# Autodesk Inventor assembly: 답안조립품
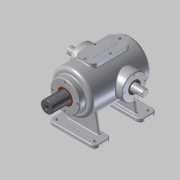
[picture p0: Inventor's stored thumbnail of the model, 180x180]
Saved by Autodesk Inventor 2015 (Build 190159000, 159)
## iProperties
Created: 2016-02
Part Number: 답안조립품
Document SubType Name: Assembly
Designer: Administrator
Mass: 4846.29 g
Surface Area: 4241.85 cm^2
Volume: 1855.51 cm^3
Density: 2.61184 g/cm^3
Author: Administrator
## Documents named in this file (15)
- C:\Users\Administrator\Desktop\360220V1013\답안조립품.iam
- C:\Users\Administrator\Desktop\360220V1013\본체.ipt
- C:\Users\Administrator\Desktop\360220V1013\상부커버.ipt
- C:\Users\Administrator\Desktop\360220V1013\육각머리볼트 M4.ipt
- C:\Users\Administrator\Desktop\360220V1013\축 커버.ipt
- C:\Users\Administrator\Desktop\360220V1013\베어링 6205.ipt
- 베어링 6205.ipt
- C:\Users\Administrator\Desktop\360220V1013\오일실.ipt
- 오일실.ipt
- C:\Users\Administrator\Desktop\360220V1013\볼트 M4x0.7.ipt
- C:\Users\Administrator\Desktop\360220V1013\슬라이드 커버.ipt
- C:\Users\Administrator\Desktop\360220V1013\부시.ipt
- C:\Users\Administrator\Desktop\360220V1013\편심축.ipt
- C:\Users\Administrator\Desktop\360220V1013\슬라이드.ipt
- C:\Users\Administrator\Desktop\360220V1013\가변스프링.ipt
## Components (13 placed, 2 different names)
1. 가변스프링:1
2. M4x0.7:1
3. M4x0.7:2
4. M4x0.7:3
5. M4x0.7:4
6. M4x0.7:5
7. M4x0.7:6
8. M4x0.7:7
9. M4x0.7:8
10. M4x0.7:9
11. M4x0.7:10
12. M4x0.7:11
13. M4x0.7:12
